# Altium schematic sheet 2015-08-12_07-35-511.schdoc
size 295 x 187 mm; SheetNumber: 1; SheetTotal: 1
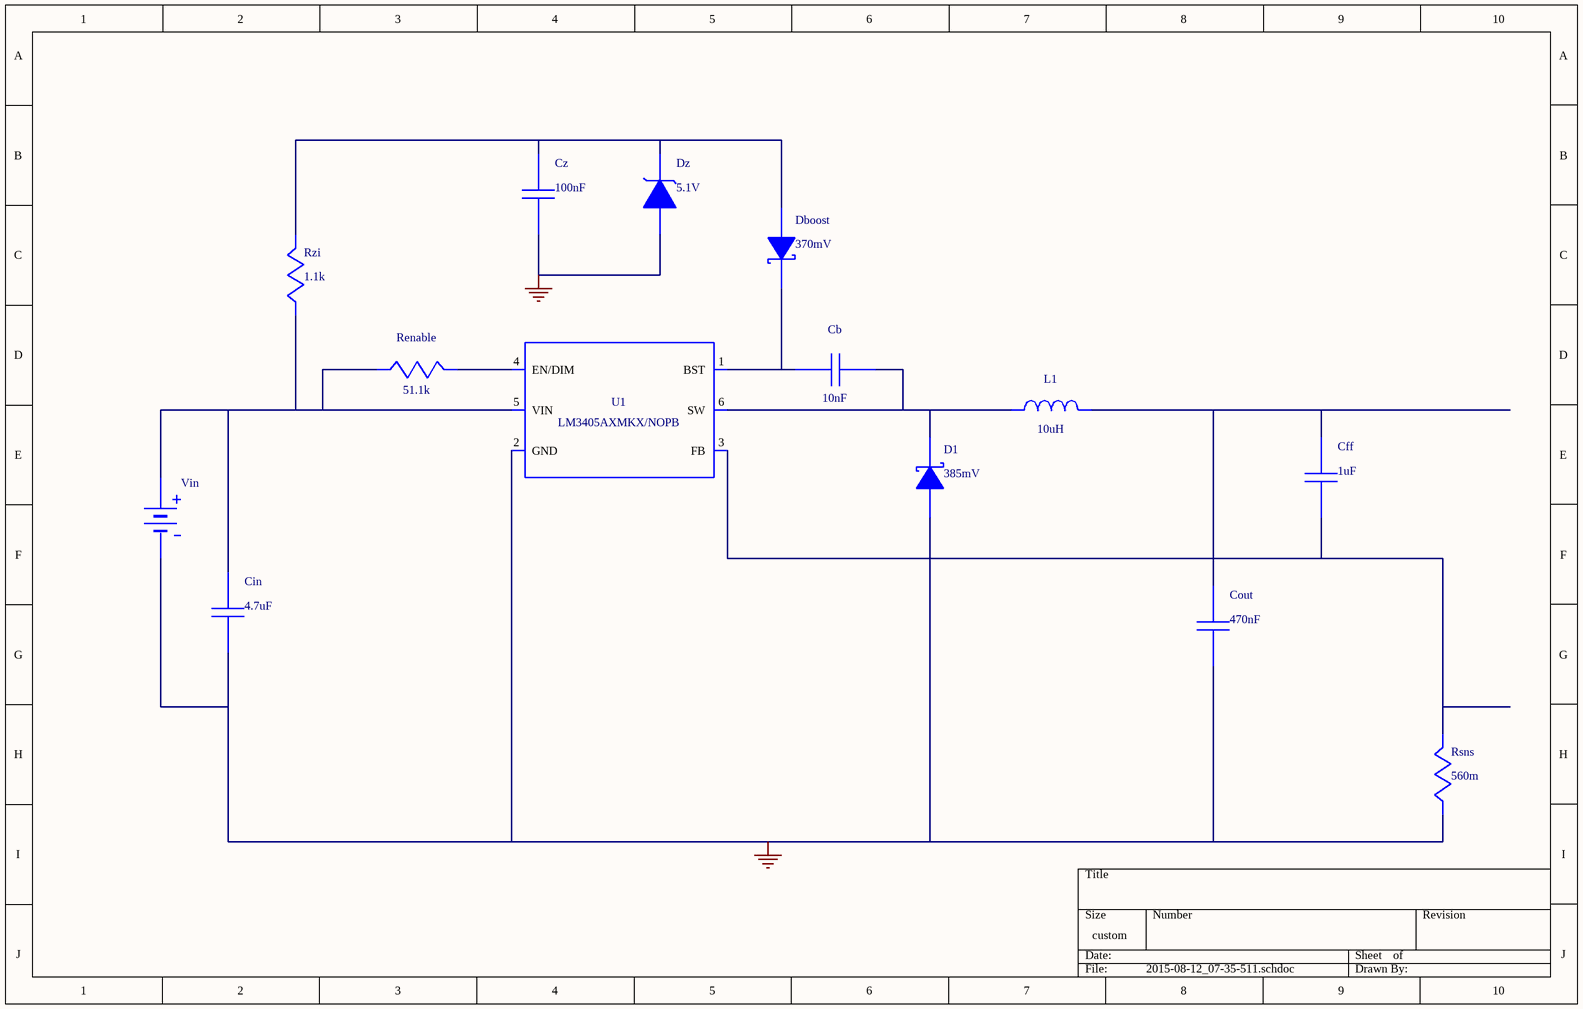
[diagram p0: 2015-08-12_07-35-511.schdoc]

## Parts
Cb  value 10nF  (hidden comment: GRM033R60J103KA01D)
Cff  value 1uF  (hidden comment: GRM21BR61C105KA01L)
Cin  value 4.7uF  (hidden comment: GRM21BR61E475MA12L)
Cout  value 470nF  (hidden comment: GRM188R70J474KA01D)
Cz  value 100nF  (hidden comment: GRM155R60J104KA01D)
D1  value 385mV  (hidden comment: MBR0520LT1G)
Dboost  value 370mV  (hidden comment: CD0603-B00340)
Dz  value 5.1V  (hidden comment: BZX84C5V1LT1G)
L1  value 10uH  (hidden comment: NLCV32T-100K-PFR)
Renable  value 51.1k  (hidden comment: CRCW040251K1FKED)
Rsns  value 560m  (hidden comment: ERJ-3RQFR56V)
Rzi  value 1.1k  (hidden comment: CRCW04021K10FKED)
U1  LM3405AXMKX/NOPB
Vin  WB_BATTERY  (value not drawn)

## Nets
0: Cin.2 Cout.2 Cz.2 D1.2(A) Dz.1(A) Rsns.2 U1.2(GND) Vin.2(-)
NetCb_1: Cb.1 D1.1(K) L1.1 U1.6(SW)
NetCb_2: Cb.2 Dboost.1(K) U1.1(BST)
NetCff_1: Cff.1 Cout.1 L1.2
NetCff_2: Cff.2 Rsns.1 U1.3(FB)
NetCin_1: Cin.1 Renable.2 Rzi.2 U1.5(VIN) Vin.1(+)
NetCz_1: Cz.1 Dboost.2(A) Dz.3(K) Rzi.1
NetRenable_1: Renable.1 U1.4(EN/DIM)

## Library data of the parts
Cb = GRM033R60J103KA01D: GRM033R60J103KA0; Manufacturer Name: MuRata
Cff = GRM21BR61C105KA01L: GRM21BR61C105KA0; Manufacturer Name: MuRata
Cin = GRM21BR61E475MA12L: GRM21BR61E475MA1; Manufacturer Name: MuRata
Cout = GRM188R70J474KA01D: GRM188R70J474KA0; Manufacturer Name: MuRata
Cz = GRM155R60J104KA01D: GRM155R60J104KA0; Manufacturer Name: MuRata
D1 = MBR0520LT1G: Manufacturer Name: ON Semiconductor
Dboost = CD0603-B00340: Manufacturer Name: Bourns
Dz = BZX84C5V1LT1G: Manufacturer Name: ON Semiconductor
L1 = NLCV32T-100K-PFR: Manufacturer Name: TDK
Renable = CRCW040251K1FKED: Manufacturer Name: Vishay-Dale
Rsns = ERJ-3RQFR56V: Manufacturer Name: Panasonic
Rzi = CRCW04021K10FKED: Manufacturer Name: Vishay-Dale
U1 = LM3405AXMKX/NOPB: Manufacturer Name: Texas Instruments; Value: UNLISTED
Vin = WB_BATTERY: Value: UNLISTED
